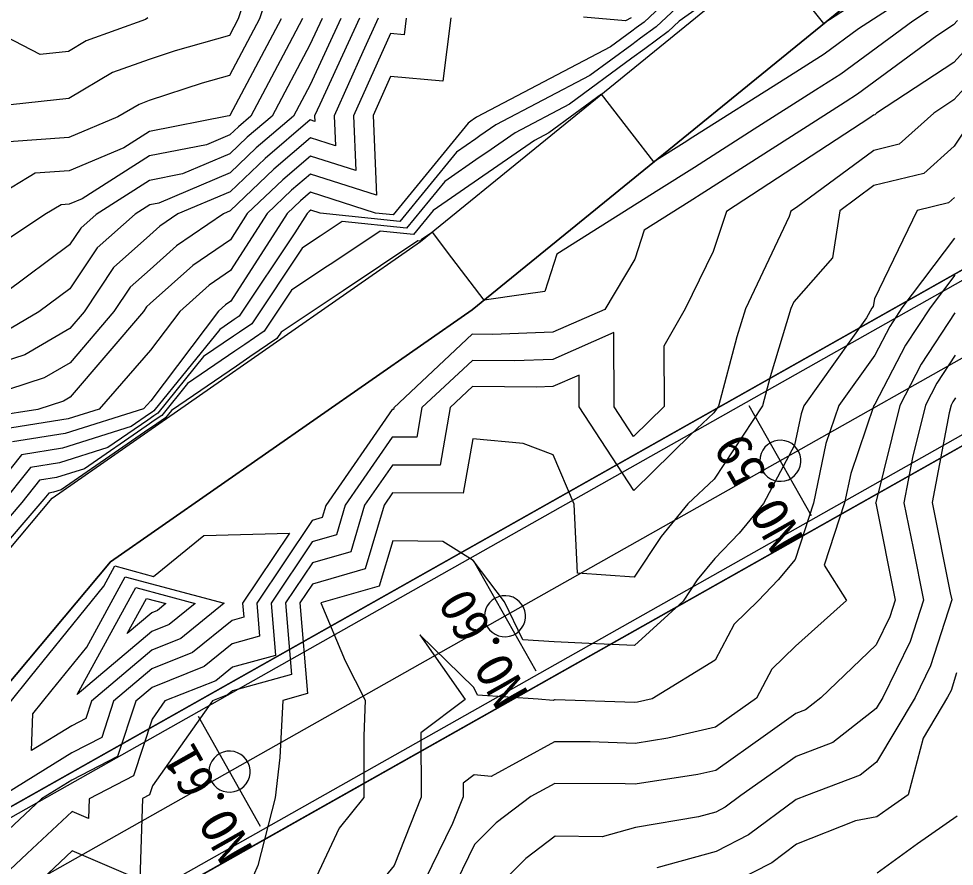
# Model space of a CAD drawing. Extents: x 42655 to 43811, y -141820 to -141156.
# Drawn here: x 42902 to 42961.1, y -141542.1 to -141488.4 of the extents above; entities that cross this region are included whole.
import ezdxf

# ---------------------------------------------------------------- set-up
doc = ezdxf.new("R2010")
doc.units = 0
for name, color, linetype in [('D-BMK-HTXT_1', 7, 'Continuous'), ('D-BMK_1', 7, 'Continuous'), ('D-STR-STR2トンネル', 7, 'Continuous'), ('ZE_HICN', 7, 'Continuous'), ('ZE_LWCN', 7, 'Continuous'), ('地形', 7, 'Continuous'), ('現況道路ﾊｯﾁ', 7, 'Continuous'), ('着色', 7, 'Continuous')]:
    doc.layers.add(name, color=color, linetype=linetype)

msp = doc.modelspace()

# ---------------------------------------------------------------- linework, layer by layer
at = {"layer": 'D-BMK-HTXT_1'}
for p, q in [((42952.097, -141519.874), (42948.164, -141512.908)), ((42934.682, -141529.709), (42930.749, -141522.743)), ((42917.267, -141539.543), (42913.334, -141532.577))]:
    msp.add_line(p, q, dxfattribs=at)
for points in [[(42948.83, -141516.391), (42948.851, -141516.623), (42948.913, -141516.848), (42949.014, -141517.058), (42949.151, -141517.246), (42949.32, -141517.408), (42949.514, -141517.536), (42949.729, -141517.628), (42949.956, -141517.679), (42950.189, -141517.69), (42950.42, -141517.659), (42950.641, -141517.587), (42950.847, -141517.476), (42951.029, -141517.331), (42951.182, -141517.155), (42951.302, -141516.955), (42951.384, -141516.737), (42951.425, -141516.508), (42951.425, -141516.275), (42951.384, -141516.045), (42951.302, -141515.827), (42951.182, -141515.627), (42951.029, -141515.451), (42950.847, -141515.306), (42950.641, -141515.196), (42950.42, -141515.124), (42950.189, -141515.092), (42949.956, -141515.103), (42949.729, -141515.155), (42949.514, -141515.246), (42949.32, -141515.375), (42949.151, -141515.536), (42949.014, -141515.724), (42948.913, -141515.934), (42948.851, -141516.159), (42948.83, -141516.391)], [(42931.415, -141526.226), (42931.436, -141526.458), (42931.498, -141526.682), (42931.599, -141526.892), (42931.736, -141527.081), (42931.905, -141527.242), (42932.099, -141527.37), (42932.314, -141527.462), (42932.541, -141527.514), (42932.774, -141527.524), (42933.005, -141527.493), (42933.226, -141527.421), (42933.432, -141527.311), (42933.614, -141527.165), (42933.767, -141526.99), (42933.887, -141526.79), (42933.969, -141526.571), (42934.01, -141526.342), (42934.01, -141526.109), (42933.969, -141525.88), (42933.887, -141525.662), (42933.767, -141525.462), (42933.614, -141525.286), (42933.432, -141525.141), (42933.226, -141525.03), (42933.005, -141524.958), (42932.774, -141524.927), (42932.541, -141524.937), (42932.314, -141524.989), (42932.099, -141525.081), (42931.905, -141525.209), (42931.736, -141525.37), (42931.599, -141525.559), (42931.498, -141525.769), (42931.436, -141525.994), (42931.415, -141526.226)], [(42914, -141536.06), (42914.021, -141536.292), (42914.083, -141536.517), (42914.184, -141536.727), (42914.321, -141536.916), (42914.49, -141537.077), (42914.684, -141537.205), (42914.899, -141537.297), (42915.126, -141537.348), (42915.359, -141537.359), (42915.59, -141537.328), (42915.811, -141537.256), (42916.017, -141537.145), (42916.199, -141537), (42916.352, -141536.824), (42916.472, -141536.624), (42916.554, -141536.406), (42916.595, -141536.177), (42916.595, -141535.944), (42916.554, -141535.714), (42916.472, -141535.496), (42916.352, -141535.296), (42916.199, -141535.121), (42916.017, -141534.975), (42915.811, -141534.865), (42915.59, -141534.793), (42915.359, -141534.762), (42915.126, -141534.772), (42914.899, -141534.824), (42914.684, -141534.915), (42914.49, -141535.044), (42914.321, -141535.205), (42914.184, -141535.393), (42914.083, -141535.603), (42914.021, -141535.828), (42914, -141536.06)]]:
    msp.add_lwpolyline(points, dxfattribs=at)
at = {"layer": 'D-BMK_1'}
msp.add_line((42932.715, -141526.226), (42777.191, -141614.053), dxfattribs=at)
msp.add_lwpolyline([(43137.071, -141410.824), (43136.635, -141411.07), (43136.2, -141411.316), (43135.765, -141411.561), (43135.329, -141411.807), (43134.894, -141412.053), (43134.458, -141412.299), (43134.023, -141412.544), (43133.587, -141412.79), (43133.152, -141413.036), (43132.717, -141413.282), (43132.281, -141413.528), (43131.846, -141413.773), (43131.41, -141414.019), (43130.975, -141414.265), (42932.715, -141526.226)], dxfattribs=at)
at = {"layer": 'D-STR-STR2トンネル'}
for p, q in [((43087.053, -141433.469), (42774.793, -141609.807)), ((43087.348, -141433.992), (42775.088, -141610.33)), ((43091.527, -141441.393), (42779.268, -141617.731)), ((43091.822, -141441.915), (42779.563, -141618.253))]:
    msp.add_line(p, q, dxfattribs=at)
at = {"layer": 'ZE_HICN'}
for points in [[(42956.468, -141486.378), (42952.885, -141488.711), (42950.368, -141485.551)], [(42947.219, -141486.108), (42943.737, -141488.576), (42943.043, -141489.233), (42941.568, -141490.316), (42940.741, -141490.922), (42936.788, -141493.825), (42933.365, -141495.63), (42931.565, -141496.872), (42931.093, -141497.198), (42928.907, -141498.707), (42926.496, -141501.66), (42922.422, -141501.244), (42921.035, -141502.168), (42920.867, -141502.28), (42919.886, -141502.934), (42916.704, -141507.714), (42915.929, -141508.242), (42915.542, -141508.506), (42913.661, -141509.79), (42910.765, -141513.373), (42910.504, -141513.554), (42910.129, -141513.813), (42907.607, -141515.559), (42904.539, -141516.525), (42902.722, -141516.813), (42900.789, -141519.224)], [(42918.559, -141488.415), (42915.317, -141494.542), (42915.283, -141494.551), (42915.156, -141494.593), (42910.234, -141495.558), (42908.622, -141496.582), (42905.157, -141498.038), (42903.001, -141498.2), (42900.078, -141499.963)], [(42924.708, -141488.386), (42923.724, -141490.511), (42921.909, -141494.562), (42921.99, -141496.469), (42920.412, -141495.964), (42918.102, -141497.934), (42915.345, -141500.575), (42914.915, -141500.757), (42911.936, -141502.792), (42910.274, -141504.282), (42909.008, -141505.407), (42907.977, -141506.952), (42905.214, -141510.188), (42903.575, -141511.145), (42900.135, -141512.258)], [(42963.412, -141491.012), (42961.106, -141493.549), (42959.838, -141494.384), (42957.65, -141496.355), (42956.033, -141496.747), (42951.149, -141500.361), (42950.8, -141500.589), (42950.689, -141500.923), (42947.916, -141506.765), (42947.378, -141508.543), (42946.211, -141512.936), (42945.934, -141513.357), (42944.487, -141514.705), (42940.869, -141518.268), (42937.415, -141512.977), (42937.406, -141510.968), (42935.75, -141511.694), (42934.713, -141511.734), (42930.662, -141511.687), (42929.245, -141513.015), (42928.609, -141516.666), (42925.597, -141516.66), (42923.843, -141519.203), (42922.966, -141522.153), (42920.538, -141522.849), (42918.838, -141525.389), (42919.218, -141529.913), (42915.487, -141530.944), (42915.179, -141531.195), (42914.226, -141531.574), (42910.427, -141536.952), (42910.239, -141537.524), (42909.791, -141537.757), (42909.618, -141542.906), (42905.358, -141541.071), (42902.292, -141543.955)], [(42961.17, -141507.026), (42959.037, -141510.274), (42957.681, -141512.882), (42956.161, -141519.024), (42956.155, -141519.052), (42956.161, -141519.081), (42957.385, -141525.209), (42957.045, -141526.269), (42956.18, -141528.046), (42952.686, -141531.394), (42951.727, -141532.145), (42951.112, -141532.379), (42949.19, -141533.745), (42946.04, -141535.979), (42944.921, -141536.236), (42940.956, -141536.86), (42940.317, -141536.841), (42935.868, -141536.815), (42934.355, -141537.642), (42932.152, -141539.3), (42930.797, -141540.678), (42929.253, -141543.829)], [(42905.662, -141531.19), (42909.376, -141524.412), (42913.12, -141525.416), (42911.477, -141526.753), (42910.381, -141527.188), (42905.662, -141531.19)]]:
    msp.add_lwpolyline(points, dxfattribs=at)
at = {"layer": 'ZE_LWCN'}
for points in [[(42917.121, -141484.501), (42915.845, -141488.427), (42915.293, -141489.47), (42911.86, -141490.445), (42910.212, -141490.987), (42907.905, -141491.828), (42905.136, -141493.473), (42900.642, -141493.944)], [(42918.096, -141485.67), (42917.202, -141488.421), (42915.305, -141492.006), (42913.572, -141492.498), (42910.225, -141493.598), (42909.577, -141493.834), (42908.245, -141494.625), (42905.147, -141495.927), (42901.345, -141496.213)], [(42944.67, -141485.644), (42941.516, -141488.624), (42941.014, -141488.992), (42940.733, -141489.199), (42939.389, -141490.186), (42930.913, -141494.653), (42930.699, -141494.801), (42930.643, -141494.839), (42930.383, -141495.019), (42925.642, -141500.824), (42924.54, -141500.712), (42920.428, -141499.393), (42919.78, -141499.946), (42918.953, -141500.738), (42915.372, -141506.295), (42915.044, -141506.52), (42914.596, -141506.921), (42910.313, -141512.593), (42909.866, -141513.106), (42904.916, -141514.663), (42901.579, -141515.193)], [(42944.203, -141487.11), (42942.279, -141488.928), (42941.291, -141489.654), (42940.737, -141490.061), (42938.089, -141492.006), (42932.139, -141495.141), (42931.132, -141495.836), (42930.868, -141496.019), (42929.645, -141496.863), (42926.069, -141501.242), (42921.031, -141500.728), (42920.433, -141500.537), (42920.339, -141500.617), (42920.219, -141500.732), (42919.422, -141501.968), (42915.913, -141507.24), (42915.599, -141507.454), (42915.443, -141507.561), (42914.681, -141508.08), (42910.521, -141513.227), (42910.402, -141513.309), (42910.23, -141513.428), (42909.079, -141514.225), (42904.728, -141515.594), (42902.151, -141516.003), (42900.164, -141518.481)], [(42958.145, -141487.046), (42955.062, -141489.055), (42952.895, -141490.65), (42950.467, -141492.19), (42944.596, -141495.913), (42944.055, -141496.261), (42942.138, -141497.472), (42940.764, -141495.711), (42938.819, -141493.199), (42935.487, -141495.645), (42934.591, -141496.118), (42931.998, -141497.908), (42931.318, -141498.377), (42928.169, -141500.551), (42926.923, -141502.077), (42924.817, -141501.863), (42921.76, -141503.899), (42921.388, -141504.147), (42919.226, -141505.587), (42917.495, -141508.188), (42916.259, -141509.031), (42915.642, -141509.452), (42912.641, -141511.501), (42911.009, -141513.519), (42910.606, -141513.798), (42910.028, -141514.199), (42906.135, -141516.894), (42904.35, -141517.455), (42903.293, -141517.623), (42902.169, -141519.026), (42901.431, -141519.889)], [(42959.823, -141487.715), (42958.502, -141488.575), (42953.955, -141491.922), (42952.35, -141492.94), (42948.47, -141495.401), (42944.707, -141497.821), (42942.449, -141499.248), (42936.005, -141503.318), (42935.245, -141505.67), (42933.878, -141505.87), (42931.392, -141506.233), (42929.366, -141503.547), (42928.128, -141501.914), (42927.431, -141502.395), (42927.35, -141502.495), (42927.212, -141502.481), (42922.484, -141505.631), (42921.909, -141506.013), (42918.566, -141508.241), (42918.285, -141508.661), (42916.589, -141509.82), (42915.742, -141510.398), (42911.621, -141513.211), (42911.253, -141513.666), (42910.709, -141514.043), (42909.926, -141514.585), (42904.663, -141518.228), (42904.162, -141518.386), (42903.865, -141518.433), (42903.549, -141518.827), (42902.302, -141520.285), (42899.328, -141523.761)], [(42910.124, -141488.362), (42909.982, -141488.455), (42906.233, -141489.822), (42905.122, -141490.482), (42903.319, -141490.67), (42900.026, -141488.968)], [(42919.915, -141488.408), (42919.074, -141490), (42916.644, -141494.586), (42915.865, -141495.25), (42915.323, -141495.77), (42913.842, -141496.397), (42910.241, -141497.103), (42905.987, -141499.804), (42905.167, -141500.148), (42904.657, -141500.187), (42903.624, -141500.81), (42900.093, -141503.154)], [(42923.524, -141488.391), (42921.004, -141493.837), (42920.677, -141494.567), (42920.691, -141494.911), (42920.407, -141494.82), (42917.543, -141497.263), (42915.34, -141499.373), (42912.04, -141500.77), (42910.9, -141501.549), (42910.264, -141502.119), (42907.968, -141504.159), (42906.1, -141506.961), (42905.204, -141508.01), (42902.351, -141509.676), (42900.127, -141510.396)], [(42961.341, -141488.526), (42961.084, -141488.808), (42960.028, -141489.505), (42955.015, -141493.194), (42954.233, -141493.69), (42952.343, -141494.889), (42945.36, -141499.38), (42944.363, -141500.01), (42941.519, -141501.806), (42940.926, -141503.641), (42939.027, -141506.807), (42935.734, -141508.251), (42931.932, -141508.398), (42930.647, -141508.383), (42925.687, -141513.032), (42925.668, -141513.138), (42925.581, -141513.138), (42921.391, -141519.215), (42921.161, -141519.988), (42920.525, -141520.17), (42917.028, -141525.398), (42917.204, -141527.496), (42915.473, -141527.974), (42913.698, -141529.418), (42910.398, -141530.73), (42909.376, -141531.596), (42908.225, -141535.108), (42905.337, -141536.604), (42903.42, -141537.787), (42900.268, -141540.714)], [(42926.477, -141488.378), (42926.346, -141489.44), (42925.469, -141489.36), (42923.141, -141494.556), (42923.289, -141498.028), (42920.417, -141497.107), (42918.662, -141498.604), (42916.422, -141500.75), (42915.354, -141502.407), (42912.972, -141504.035), (42910.285, -141506.444), (42910.048, -141506.654), (42909.855, -141506.943), (42905.224, -141512.365), (42904.799, -141512.614), (42903.181, -141513.137), (42900.437, -141513.573)], [(42929.288, -141488.364), (42928.794, -141492.377), (42925.482, -141492.074), (42924.373, -141494.55), (42924.587, -141499.586), (42920.423, -141498.25), (42919.221, -141499.275), (42917.688, -141500.744), (42915.363, -141504.351), (42914.008, -141505.277), (42912.161, -141506.933), (42910.298, -141509.4), (42907.055, -141513.119), (42905.105, -141513.733), (42901.008, -141514.383)], [(42921.158, -141488.402), (42920.384, -141490.073), (42917.997, -141494.58), (42916.425, -141495.921), (42915.329, -141496.971), (42912.336, -141498.238), (42910.248, -141498.647), (42906.866, -141500.795), (42905.888, -141501.663), (42905.179, -141502.727), (42901.111, -141505.766)], [(42922.341, -141488.397), (42920.396, -141492.599), (42919.35, -141494.574), (42916.984, -141496.592), (42915.334, -141498.172), (42910.83, -141500.079), (42910.255, -141500.192), (42909.324, -141500.783), (42906.928, -141502.911), (42905.192, -141505.515), (42903.239, -141506.974), (42901.127, -141508.208)], [(42940.69, -141488.366), (42940.329, -141488.556), (42937.676, -141488.325)], [(42962.376, -141489.769), (42961.095, -141491.179), (42956.204, -141494.401), (42956.1, -141494.495), (42956.023, -141494.514), (42955.79, -141494.686), (42946.73, -141500.608), (42945.887, -141503.15), (42944.108, -141506.783), (42942.756, -141509.127), (42942.774, -141512.952), (42940.853, -141514.844), (42939.628, -141512.967), (42939.606, -141508.278), (42935.742, -141509.973), (42933.323, -141510.066), (42930.654, -141510.035), (42927.466, -141513.024), (42927.139, -141514.902), (42925.589, -141514.899), (42922.617, -141519.209), (42922.064, -141521.07), (42920.531, -141521.51), (42917.933, -141525.394), (42918.211, -141528.704), (42915.48, -141529.459), (42914.439, -141530.306), (42911.215, -141531.588), (42910.407, -141532.731), (42909.232, -141536.316), (42906.421, -141537.773), (42906.379, -141539.021), (42905.346, -141538.576), (42902.502, -141541.251), (42900.28, -141543.314)], [(42962.524, -141494.372), (42961.12, -141496.487), (42959.201, -141498.216), (42956.044, -141498.979), (42953.888, -141500.575), (42953.431, -141503.55), (42950.99, -141506.332), (42950.791, -141506.752), (42949.483, -141511.069), (42948.991, -141512.923), (42945.954, -141517.549), (42944.28, -141519.108), (42942.586, -141521.179), (42940.895, -141523.746), (42937.293, -141523.501), (42937.095, -141519.141), (42935.77, -141516.006), (42933.868, -141515.293), (42930.677, -141514.997), (42930.079, -141518.43), (42925.605, -141518.42), (42925.069, -141519.198), (42923.869, -141523.236), (42920.544, -141524.189), (42919.744, -141525.385), (42920.226, -141531.121), (42918.663, -141531.553), (42918.488, -141535.164), (42918.181, -141537.718), (42917.091, -141542.005), (42916.269, -141543.889)], [(42961.135, -141499.73), (42960.752, -141500.076), (42958.784, -141500.552), (42956.077, -141506.149), (42956.003, -141506.635), (42955.921, -141506.728), (42955.574, -141507.346), (42951.618, -141512.911), (42951.444, -141513.422), (42951.032, -141515.397), (42949.073, -141519.085), (42947.519, -141520.968), (42945.978, -141522.566), (42944.871, -141523.92), (42943.979, -141525.272), (42940.915, -141528.071), (42938.021, -141527.957), (42935.826, -141527.856), (42933.842, -141527.722), (42932.679, -141525.325), (42930.713, -141522.71), (42928.791, -141521.501), (42925.619, -141521.465), (42924.771, -141524.318), (42921.073, -141525.379), (42922.621, -141529.046), (42923.886, -141531.528), (42923.783, -141533.824), (42923.801, -141537.692), (42922.222, -141539.643), (42920.632, -141543.053)], [(42961.147, -141502.298), (42957.812, -141506.719), (42957.046, -141507.886), (42956.094, -141509.716), (42953.83, -141512.9), (42953.014, -141515.305), (42952.228, -141519.071), (42951.066, -141522.631), (42949.991, -141523.934), (42948.722, -141525.25), (42947.204, -141526.719), (42946.008, -141529.004), (42942.021, -141531.444), (42941.103, -141531.655), (42940.932, -141531.682), (42935.887, -141531.526), (42935.843, -141531.525), (42935.764, -141531.568), (42934.825, -141531.477), (42930.983, -141531.217), (42930.751, -141530.738), (42927.343, -141527.404), (42930.197, -141531.499), (42927.399, -141533.598), (42927.418, -141537.675), (42925.715, -141541.99), (42924.958, -141542.926)], [(42961.158, -141504.641), (42959.597, -141506.711), (42958.041, -141509.08), (42956.108, -141512.797), (42956.042, -141512.89), (42954.584, -141517.188), (42954.193, -141519.061), (42952.906, -141523.004), (42954.316, -141525.224), (42951.092, -141528.115), (42949.584, -141529.574), (42948.621, -141531.413), (42946.027, -141533.252), (42943.012, -141533.946), (42940.944, -141534.271), (42938.102, -141534.183), (42935.855, -141534.17), (42931.842, -141536.364), (42930.777, -141536.261), (42930.064, -141536.796), (42930.068, -141537.662), (42929.404, -141539.346), (42927.201, -141543.838)], [(42961.182, -141509.717), (42960.032, -141511.469), (42959.301, -141512.875), (42958.482, -141516.186), (42957.941, -141519.044), (42958.519, -141521.91), (42959.176, -141525.201), (42958.337, -141527.819), (42956.606, -141531.375), (42956.198, -141532.058), (42953.45, -141534.212), (42951.124, -141535.093), (42947.628, -141537.58), (42946.649, -141538.309), (42946.053, -141538.615), (42944.962, -141538.915), (42940.969, -141539.591), (42938.859, -141540.18), (42935.883, -141540.151), (42934.026, -141541.549), (42931.797, -141543.817)], [(42961.195, -141512.408), (42961.028, -141512.663), (42960.921, -141512.867), (42960.802, -141513.348), (42959.726, -141519.036), (42960.877, -141524.738), (42960.968, -141525.192), (42959.629, -141529.369), (42958.657, -141531.366), (42956.214, -141535.463), (42955.173, -141536.279), (42951.79, -141537.561), (42951.137, -141537.819), (42948.115, -141540.068), (42946.064, -141541.12), (42942.313, -141542.154)], [(42899.687, -141538.495), (42899.44, -141537.805), (42899.584, -141537.609), (42899.691, -141537.464), (42899.96, -141537.097), (42900.125, -141533.269), (42902.714, -141530.057), (42907.344, -141524.315), (42908.038, -141523.048), (42910.487, -141523.704), (42913.672, -141521.127), (42919.082, -141520.978), (42916.122, -141525.402), (42916.197, -141526.287), (42915.466, -141526.489), (42912.958, -141528.529), (42910.392, -141529.549), (42907.97, -141531.603), (42907.218, -141533.899), (42905.329, -141534.878), (42900.594, -141537.8), (42900.256, -141538.114), (42899.687, -141538.495)], [(42902.77, -141534.726), (42902.87, -141532.394), (42904.09, -141530.882), (42906.27, -141528.178), (42908.707, -141523.73), (42914.964, -141525.407), (42912.217, -141527.641), (42910.387, -141528.368), (42906.565, -141531.609), (42906.21, -141532.691), (42905.321, -141533.152), (42902.77, -141534.726)], [(42908.824, -141527.323), (42910.045, -141525.095), (42911.277, -141525.425), (42910.736, -141525.864), (42910.376, -141526.007), (42908.824, -141527.323)], [(42961.276, -141529.813), (42960.922, -141530.92), (42960.709, -141531.356), (42959.169, -141533.939), (42958.208, -141537.531), (42956.947, -141538.407), (42956.23, -141538.929), (42954.882, -141539.181), (42951.15, -141540.659), (42949.581, -141541.827), (42946.076, -141543.625)], [(42961.319, -141538.882), (42958.801, -141540.632), (42956.247, -141542.491)]]:
    msp.add_lwpolyline(points, dxfattribs=at)
at = {"layer": '地形'}
for points in [[(42849.542, -141623.849), (42851.871, -141623.689), (42857.399, -141617.615), (42865.364, -141603.011), (42875.126, -141582.286), (42879.7, -141567.56), (42884.865, -141548.774), (42890.476, -141535.001), (42904.088, -141518.749), (42927.38, -141502.524), (42957.635, -141477.86), (42972.865, -141465.444), (42992.716, -141449.637), (43009.337, -141439.992), (43032.561, -141430.139), (43054.789, -141429.742)], [(42848.997, -141630.72), (42853.225, -141629.019), (42860.5, -141623.012), (42870.042, -141605.732), (42880.634, -141583.758), (42885.71, -141567.43), (42888.598, -141549.639), (42895.166, -141537.825), (42907.772, -141522.776), (42930.639, -141506.846), (42961.053, -141482.053), (42976.259, -141469.657), (42995.775, -141454.117), (43011.761, -141444.84), (43033.707, -141435.529)]]:
    msp.add_lwpolyline(points, dxfattribs=at)
at = {"layer": '現況道路ﾊｯﾁ'}
for points in [[(42833.01, -141585.023), (42837.144, -141587.724), (42841.597, -141588.35), (42849.632, -141593.502), (42851.984, -141599.859), (42849.738, -141607.719), (42847.19, -141614.061), (42846.534, -141618.245), (42846.996, -141622.369), (42849.542, -141623.849), (42851.871, -141623.689), (42857.295, -141617.729), (42865.364, -141603.011), (42875.126, -141582.286), (42879.7, -141567.56), (42884.865, -141548.774), (42890.476, -141535.001), (42904.088, -141518.749), (42927.38, -141502.524), (42957.635, -141477.86), (42992.716, -141449.637), (43009.337, -141439.992), (43032.561, -141430.139), (43054.789, -141429.742)], [(43033.707, -141435.529), (43011.761, -141444.84), (42995.775, -141454.117), (42961.053, -141482.053), (42930.639, -141506.846), (42907.772, -141522.776), (42895.166, -141537.825), (42888.598, -141549.639), (42885.71, -141567.43), (42880.634, -141583.758), (42870.042, -141605.732), (42860.5, -141623.012), (42853.225, -141629.019), (42848.997, -141630.72), (42842.739, -141630.086), (42840.643, -141625.494), (42840.152, -141617.792), (42840.702, -141613.645), (42843.437, -141605.138), (42843.326, -141600.509), (42842.734, -141598.733), (42839.012, -141595.856), (42835.966, -141595.687)]]:
    msp.add_lwpolyline(points, dxfattribs=at)
at = {"layer": '着色'}
msp.add_lwpolyline([(42779.563, -141618.253), (43091.823, -141441.915), (43087.053, -141433.469), (42774.793, -141609.807)], close=True, dxfattribs=at)

# ---------------------------------------------------------------- texts
at = {"layer": 'D-BMK-HTXT_1'}
for s, p in [('NO.59', (42951.653, -141521.273)), ('NO.60', (42934.238, -141531.108)), ('NO.61', (42916.823, -141540.943))]:
    msp.add_text(s, height=2.3065, rotation=119.45336, dxfattribs=at).set_placement(p)

doc.saveas('drawing.dxf')
